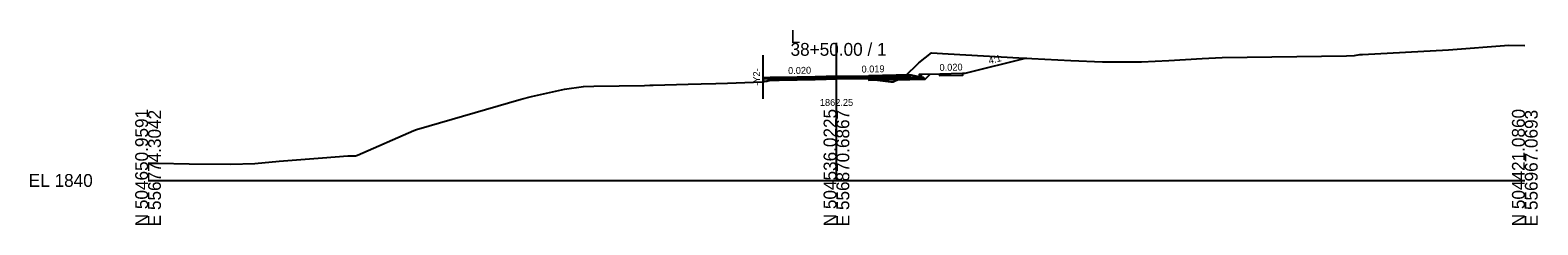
# Model space of a CAD drawing. Extents: x -26 to 4603, y -10 to 4703.
# Drawn here: x 974.3 to 1302.8, y 4165.3 to 4207.8 of the extents above; entities that cross this region are included whole.
import ezdxf

# ---------------------------------------------------------------- set-up
doc = ezdxf.new("R2010")
doc.units = 0
for name, color, linetype in [('Default', 7, 'Continuous'), ('Exist Cross Section Cell', 7, 'Continuous'), ('Exist XS Ground Line', 7, 'Continuous'), ('Prop CMT Pvmt Course 1', 7, 'Continuous'), ('Prop CMT Pvmt Course 2', 7, 'Continuous'), ('Prop CMT Pvmt Course 3', 7, 'Continuous'), ('Prop CMT Pvmt Milling', 7, 'Continuous'), ('Prop CMT Shear Line', 7, 'Continuous'), ('Prop CMT Shld Paved Course 2', 7, 'Continuous'), ('Prop CMT Subgrade Earthwork', 7, 'Continuous'), ('Prop Conc 4in Sidewalk', 7, 'Continuous'), ('Prop Conc Curb and Gutter', 7, 'Continuous'), ('Prop Corridor Mesh Bottom', 7, 'Continuous'), ('Prop XS Finish Grade', 7, 'Continuous'), ('Prop XS Label Text', 7, 'Continuous'), ('Prop XS Shear Point Element', 7, 'Continuous'), ('Prop XS Shear Point Label', 7, 'Continuous'), ('Prop XS SS Elevation Text', 7, 'Continuous')]:
    doc.layers.add(name, color=color, linetype=linetype)

msp = doc.modelspace()

# ---------------------------------------------------------------- linework, layer by layer
at = {"layer": 'Exist Cross Section Cell'}
for p, q in [((1150, 4175), (1150, 4205)), ((1000, 4175), (1150, 4175)), ((1150, 4175), (1300, 4175))]:
    msp.add_line(p, q, dxfattribs=at)
at = {"layer": 'Exist XS Ground Line'}
msp.add_lwpolyline([(1000, 4178.79), (1002.2, 4178.76), (1008.95, 4178.66), (1017.93, 4178.53), (1023.3, 4178.68), (1028.58, 4179.18), (1038.04, 4179.93), (1043.53, 4180.35), (1045.19, 4180.39), (1045.61, 4180.5), (1057.91, 4185.89), (1058.46, 4186.14), (1081.31, 4192.72), (1083.55, 4193.29), (1090.77, 4194.9), (1094.88, 4195.53), (1097.15, 4195.59), (1108.21, 4195.73), (1109.35, 4195.78), (1110.08, 4195.8), (1117.72, 4195.98), (1120.54, 4196.05), (1123.73, 4196.16), (1126.28, 4196.19), (1131.94, 4196.47), (1133.83, 4196.54), (1134.8, 4196.68), (1135.58, 4196.87), (1137.52, 4196.96), (1145.38, 4197.23), (1147.74, 4197.26), (1150.97, 4197.24), (1157.05, 4197.22), (1157.24, 4197.12), (1161.86, 4196.54), (1162.33, 4196.49), (1162.66, 4196.67), (1164.88, 4197.65), (1167.97, 4200.69), (1170.68, 4202.85), (1174.32, 4202.64), (1189.72, 4201.75), (1201.08, 4201.17), (1207.97, 4200.87), (1216.49, 4200.88), (1222.45, 4201.15), (1229.71, 4201.59), (1234.02, 4201.85), (1261.13, 4202.21), (1262.92, 4202.24), (1264.05, 4202.47), (1264.62, 4202.47), (1283.39, 4203.47), (1296.52, 4204.53), (1300, 4204.43)], dxfattribs=at)
at = {"layer": 'Prop CMT Pvmt Course 1'}
for points in [[(1150, 4197.73), (1147.74, 4197.68), (1147.74, 4197.68), (1147.74, 4197.68), (1145.38, 4197.63), (1145.38, 4197.63), (1137.52, 4197.48), (1135.58, 4197.44), (1135.58, 4197.44), (1134.8, 4197.42), (1134.8, 4197.42), (1134, 4197.41), (1134, 4197.41), (1134, 4196.56), (1134, 4196.56), (1134, 4196.56), (1134.8, 4196.68), (1134.8, 4196.68), (1135.58, 4196.87), (1135.58, 4196.87), (1137.52, 4196.96), (1145.38, 4197.23), (1145.38, 4197.23), (1147.74, 4197.26), (1147.74, 4197.26), (1147.74, 4197.26), (1150, 4197.25), (1150, 4197.25), (1150, 4197.25), (1150, 4197.73), (1150, 4197.73)], [(1157.05, 4197.86), (1157.05, 4197.22), (1157.05, 4197.22), (1150.97, 4197.24), (1150.97, 4197.24), (1150, 4197.25), (1150, 4197.25), (1150, 4197.73), (1150.97, 4197.74), (1150.97, 4197.74), (1157.05, 4197.86)], [(1166, 4198.02), (1157.05, 4197.86), (1157.05, 4197.61), (1157.05, 4197.61), (1166, 4197.77), (1166, 4197.77), (1166, 4197.77), (1166, 4198.02), (1166, 4198.02)]]:
    msp.add_lwpolyline(points, dxfattribs=at)
at = {"layer": 'Prop CMT Pvmt Course 2'}
msp.add_lwpolyline([(1166, 4197.77), (1157.05, 4197.61), (1157.05, 4197.27), (1157.05, 4197.27), (1166, 4197.44), (1166, 4197.44), (1166, 4197.44), (1166, 4197.77), (1166, 4197.77)], dxfattribs=at)
at = {"layer": 'Prop CMT Pvmt Course 3'}
for points in [[(1166, 4197.44), (1157.05, 4197.27), (1157.05, 4196.9), (1157.05, 4196.9), (1166, 4197.06), (1166, 4197.06), (1166, 4197.06), (1166, 4197.44), (1166, 4197.44)], [(1166, 4197.44), (1166, 4197.44), (1166, 4197.06), (1166, 4197.06), (1166, 4197.06), (1169.37, 4197.13), (1169.37, 4197.13), (1169, 4197.49), (1166, 4197.44)]]:
    msp.add_lwpolyline(points, dxfattribs=at)
at = {"layer": 'Prop CMT Pvmt Milling'}
for points in [[(1150, 4197.25), (1150, 4197.25), (1147.74, 4197.26), (1147.74, 4197.26), (1147.74, 4197.26), (1145.38, 4197.23), (1145.38, 4197.23), (1137.52, 4196.96), (1135.58, 4196.87), (1135.58, 4196.87), (1134.8, 4196.68), (1134.8, 4196.68), (1134, 4196.56), (1134, 4196.56)], [(1157.05, 4197.22), (1150.97, 4197.24), (1150.97, 4197.24), (1150, 4197.25)]]:
    msp.add_lwpolyline(points, dxfattribs=at)
at = {"layer": 'Prop CMT Shld Paved Course 2'}
for points in [[(1150, 4197.48), (1147.74, 4197.43), (1147.74, 4197.43), (1147.74, 4197.43), (1145.38, 4197.38), (1145.38, 4197.38), (1137.52, 4197.23), (1135.58, 4197.19), (1135.58, 4197.19), (1134.8, 4197.17), (1134.8, 4197.17), (1134, 4197.16), (1134, 4197.16), (1134, 4196.56), (1134, 4196.56), (1134, 4196.56), (1134.8, 4196.68), (1134.8, 4196.68), (1135.49, 4196.85), (1135.49, 4196.85), (1135.58, 4196.85), (1135.58, 4196.85), (1137.52, 4196.89), (1145.38, 4197.05), (1145.38, 4197.05), (1147.74, 4197.1), (1147.74, 4197.1), (1147.74, 4197.1), (1150, 4197.14), (1150, 4197.14), (1150, 4197.14), (1150, 4197.48), (1150, 4197.48)], [(1157.05, 4197.61), (1157.05, 4197.22), (1157.05, 4197.22), (1157.05, 4197.22), (1154.71, 4197.23), (1150.97, 4197.16), (1150.97, 4197.16), (1150, 4197.14), (1150, 4197.14), (1150, 4197.48), (1150.97, 4197.49), (1150.97, 4197.49), (1157.05, 4197.61)]]:
    msp.add_lwpolyline(points, dxfattribs=at)
at = {"layer": 'Prop CMT Subgrade Earthwork'}
for points in [[(1169.37, 4197.13), (1169.37, 4197.13), (1157.05, 4196.9)], [(1170.4, 4198.16), (1169.37, 4197.13), (1169.37, 4197.13)]]:
    msp.add_lwpolyline(points, dxfattribs=at)
at = {"layer": 'Prop Conc 4in Sidewalk'}
msp.add_lwpolyline([(1172.5, 4198.2), (1172.5, 4198.2), (1172.49, 4197.87), (1172.49, 4197.87), (1172.49, 4197.87), (1177.51, 4197.97), (1177.51, 4197.97), (1177.5, 4198.3), (1172.5, 4198.2)], dxfattribs=at)
at = {"layer": 'Prop Conc Curb and Gutter'}
msp.add_lwpolyline([(1168, 4197.62), (1166, 4198.02), (1166, 4197.44), (1166, 4197.44), (1166, 4197.44), (1168.5, 4197.48), (1168.5, 4197.48), (1168.5, 4198.12), (1168.5, 4198.12), (1168, 4198.12), (1168, 4197.62), (1168, 4197.62), (1168, 4197.62)], dxfattribs=at)
at = {"layer": 'Prop Corridor Mesh Bottom'}
msp.add_lwpolyline([(1166, 4198.02), (1166, 4197.77)], dxfattribs=at)
at = {"layer": 'Prop XS Finish Grade'}
for points in [[(1191.41, 4201.66), (1178, 4198.31), (1178, 4198.31)], [(1172.5, 4198.2), (1168.5, 4198.12), (1168.5, 4198.12)], [(1178, 4198.31), (1177.5, 4198.3), (1177.5, 4198.3)]]:
    msp.add_lwpolyline(points, dxfattribs=at)
at = {"layer": 'Prop XS Shear Point Element'}
msp.add_line((1134, 4192.81), (1134, 4202.3), dxfattribs=at)

# ---------------------------------------------------------------- texts
at = {"layer": 'Default'}
msp.add_text('-', height=0.0001, dxfattribs=at).set_placement((1000, 4175))
at = {"layer": 'Exist Cross Section Cell'}
for s, p in [('L', (1140, 4205)), ('38+50.00 / 1', (1140, 4202.2)), ('EL 1840', (974, 4173.6))]:
    msp.add_text(s, height=2.8, dxfattribs=at).set_placement(p)
for s, p in [('N 504650.9591', (1000, 4165)), ('E 556774.3042', (1002.8, 4165)), ('N 504536.0225', (1150, 4165)), ('E 556870.6867', (1152.8, 4165)), ('N 504421.0860', (1300, 4165)), ('E 556967.0693', (1302.8, 4165))]:
    msp.add_text(s, height=2.8, rotation=90, dxfattribs=at).set_placement(p)
at = {"layer": 'Prop CMT Shear Line'}
for p in [(1191.41, 4201.66), (1134, 4197.4), (1150, 4197.72), (1166, 4198.02), (1166, 4198.02), (1168, 4197.62), (1172.5, 4198.2), (1177.5, 4198.3), (1178, 4198.31)]:
    msp.add_text('X', height=0.0025, dxfattribs=at).set_placement(p)
at = {"layer": 'Prop XS Label Text'}
for s, rotation, p in [('4:1', 14.0362, (1183.34, 4200.37)), ('0.020', 1.1458, (1139.48, 4198.21)), ('0.019', 1.061, (1155.48, 4198.53)), ('0.020', 1.1458, (1172.48, 4198.9))]:
    msp.add_text(s, height=1.5, rotation=rotation, dxfattribs=at).set_placement(p)
at = {"layer": 'Prop XS Shear Point Label'}
msp.add_text('-Y2-', height=1.5, rotation=90, dxfattribs=at).set_placement((1133.33, 4195.67))
at = {"layer": 'Prop XS SS Elevation Text'}
msp.add_text('1862.25', height=1.5, dxfattribs=at).set_placement((1146.39, 4191.27))

doc.saveas('drawing.dxf')
